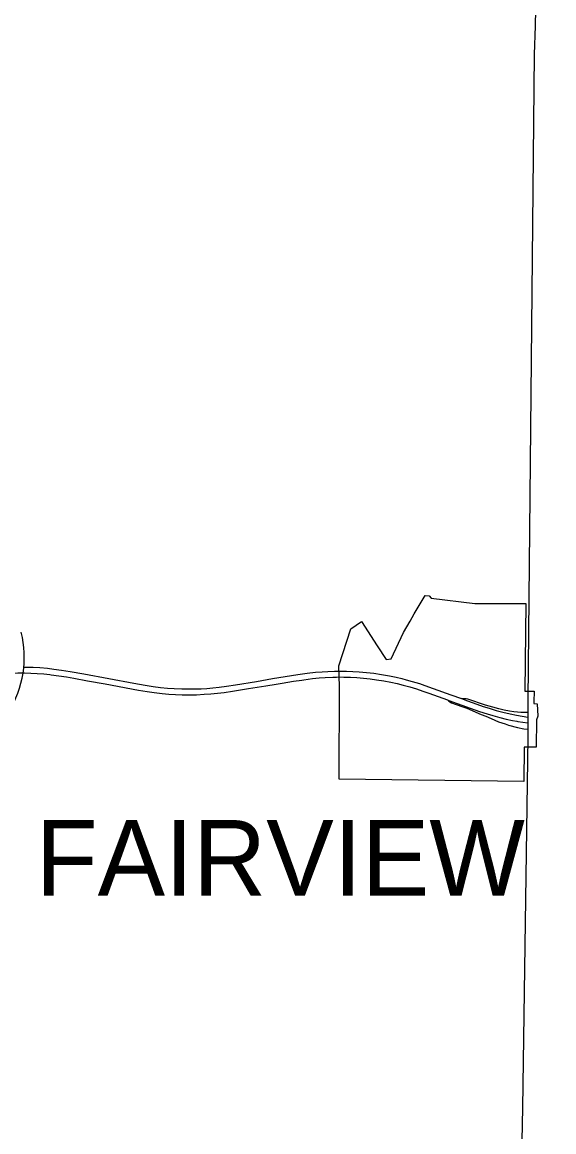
# Model space of a CAD drawing. Extents: x 1913970 to 2397567, y 78841 to 829347.
# Drawn here: x 2316499 to 2324369, y 745015 to 761443 of the extents above; entities that cross this region are included whole.
import ezdxf

# ---------------------------------------------------------------- set-up
doc = ezdxf.new("R2010")
doc.units = 0
for name, color, linetype in [('GM_X_Corporation', 7, 'Continuous'), ('GM_X_Corporation_Text', 7, 'Continuous'), ('GM_X_County', 7, 'Continuous'), ('GM_X_Interstate_Route', 7, 'Continuous'), ('GM_X_Interstate_Shield', 7, 'Continuous'), ('UT_P_Electric', 7, 'Continuous')]:
    doc.layers.add(name, color=color, linetype=linetype)

msp = doc.modelspace()

# ---------------------------------------------------------------- linework, layer by layer
at = {"layer": 'GM_X_Corporation'}
msp.add_lwpolyline([(2321188, 751913), (2321365, 752464), (2321521, 752570), (2321754, 752210), (2321887, 752009), (2321963, 752018), (2322144, 752405), (2322245, 752573), (2322303, 752684), (2322466, 752956), (2322522, 752949), (2322555, 752914), (2323198, 752837), (2323954, 752835), (2323938, 751538), (2324080, 751538), (2324073, 751383), (2324072, 751356), (2324123, 751353), (2324135, 751167), (2324115, 751113), (2324110, 750712), (2323930, 750710), (2323925, 750203), (2321191, 750235), (2321195, 751610)], close=True, dxfattribs=at)
at = {"layer": 'GM_X_County'}
msp.add_lwpolyline([(2324369, 779084), (2324336, 777711), (2324310, 776695), (2324256, 773858), (2324222, 769713), (2324164, 766356), (2324112, 762364), (2324091, 761387), (2324077, 760963), (2323984, 751408), (2323984, 751226), (2323984, 751159), (2323984, 751073), (2323984, 750978), (2323984, 750856), (2323908, 745369), (2323896, 744883)], dxfattribs=at)
at = {"layer": 'GM_X_Interstate_Route'}
for points in [[(2315028, 751513), (2315142, 751557), (2315263, 751601), (2315365, 751636), (2315459, 751665), (2315554, 751691), (2315656, 751715), (2315756, 751736), (2315853, 751754), (2315950, 751769), (2316045, 751782), (2316139, 751793), (2316231, 751800), (2316336, 751806), (2316434, 751809), (2316533, 751809), (2316628, 751806), (2316723, 751801), (2316821, 751793), (2316909, 751784)], [(2316909, 751784), (2316929, 751782), (2317040, 751767), (2317157, 751749), (2317263, 751731), (2317467, 751693), (2317728, 751645), (2318222, 751554), (2318348, 751533), (2318455, 751518), (2318572, 751505), (2318670, 751496), (2318768, 751489), (2318869, 751486), (2318971, 751485), (2319082, 751487), (2319194, 751492), (2319292, 751499), (2319390, 751507), (2319487, 751519), (2319611, 751537), (2319850, 751577), (2320106, 751619), (2320258, 751644), (2320349, 751658), (2320514, 751685), (2320638, 751704)], [(2320638, 751704), (2320669, 751709), (2320796, 751725), (2320894, 751735), (2320983, 751742), (2321098, 751747), (2321152, 751748), (2321183, 751749)], [(2321183, 751749), (2321188, 751749), (2321263, 751748), (2321360, 751745), (2321455, 751739), (2321554, 751731), (2321651, 751720), (2321746, 751707), (2321853, 751690), (2321959, 751671), (2322052, 751650), (2322141, 751628), (2322239, 751601), (2322337, 751572), (2322430, 751541), (2322520, 751509), (2322796, 751409)], [(2322796, 751409), (2322816, 751402), (2323130, 751289), (2323270, 751240), (2323385, 751203), (2323469, 751177), (2323570, 751150), (2323666, 751126), (2323759, 751106), (2323823, 751093), (2323839, 751090), (2323985, 751070)]]:
    msp.add_lwpolyline(points, dxfattribs=at)
at = {"layer": 'GM_X_Interstate_Shield'}
msp.add_arc((2315022, 752040), 1509, 281.537, 14.1934, dxfattribs=at)
at = {"layer": 'UT_P_Electric'}
for points in [[(2316514, 751809), (2316533, 751809), (2316628, 751806), (2316723, 751801), (2316821, 751793), (2316909, 751784)], [(2316524, 751896), (2316558, 751895), (2316663, 751892), (2316761, 751887), (2316872, 751878), (2316970, 751866), (2317080, 751850), (2317209, 751829), (2317410, 751793), (2318152, 751656), (2318320, 751626), (2318440, 751608), (2318547, 751595), (2318652, 751585), (2318750, 751578), (2318862, 751573), (2318974, 751571), (2319062, 751572), (2319148, 751575), (2319233, 751580), (2319321, 751587), (2319416, 751598), (2319523, 751612), (2319657, 751632), (2319967, 751684), (2320207, 751724), (2320582, 751784), (2320719, 751803), (2320842, 751818), (2320940, 751826), (2321025, 751831), (2321125, 751834), (2321186, 751834), (2321257, 751834), (2321299, 751834), (2321394, 751831), (2321489, 751825), (2321596, 751816), (2321707, 751803), (2321817, 751786), (2321939, 751765), (2322036, 751745), (2322119, 751726), (2322182, 751709), (2322270, 751684), (2322380, 751650), (2322460, 751623), (2322584, 751579), (2322847, 751486), (2323004, 751428)], [(2316909, 751784), (2316929, 751782), (2317040, 751767), (2317157, 751749), (2317263, 751731), (2317467, 751693), (2317728, 751645), (2318222, 751554), (2318348, 751533), (2318455, 751518), (2318572, 751505), (2318670, 751496), (2318768, 751489), (2318869, 751486), (2318971, 751485), (2319082, 751487), (2319194, 751492), (2319292, 751499), (2319390, 751507), (2319487, 751519), (2319611, 751537), (2319850, 751577), (2320106, 751619), (2320258, 751644), (2320349, 751658), (2320514, 751685), (2320638, 751704)], [(2320638, 751704), (2320669, 751709), (2320796, 751725), (2320894, 751735), (2320983, 751742), (2321098, 751747), (2321152, 751748), (2321183, 751749)], [(2321183, 751749), (2321188, 751749), (2321263, 751748), (2321360, 751745), (2321455, 751739), (2321554, 751731), (2321651, 751720), (2321746, 751707), (2321853, 751690), (2321959, 751671), (2322052, 751650), (2322141, 751628), (2322239, 751601), (2322337, 751572), (2322430, 751541), (2322520, 751509), (2322796, 751409)], [(2322796, 751409), (2322817, 751390), (2322831, 751381), (2322856, 751368), (2323009, 751312), (2323080, 751285), (2323295, 751195), (2323361, 751167), (2323440, 751134), (2323552, 751087), (2323648, 751053), (2323697, 751037), (2323830, 751003), (2323926, 750983), (2323985, 750976)], [(2322796, 751409), (2322816, 751402), (2323130, 751289), (2323270, 751240), (2323385, 751203), (2323469, 751177), (2323570, 751150), (2323666, 751126), (2323759, 751106), (2323823, 751093), (2323839, 751090), (2323985, 751070)], [(2323985, 751223), (2323881, 751223), (2323832, 751226), (2323776, 751232), (2323711, 751243), (2323634, 751258), (2323554, 751277), (2323469, 751300), (2323359, 751333), (2323095, 751419), (2323070, 751425), (2323039, 751427), (2323004, 751428)], [(2323004, 751428), (2323093, 751395), (2323229, 751346), (2323322, 751314), (2323413, 751286), (2323517, 751255), (2323615, 751229), (2323721, 751204), (2323817, 751184), (2323901, 751168), (2323985, 751156)]]:
    msp.add_lwpolyline(points, dxfattribs=at)

# ---------------------------------------------------------------- texts
at = {"layer": 'GM_X_Corporation_Text'}
msp.add_text('FAIRVIEW', height=1120, rotation=0, dxfattribs=at).set_placement((2316701, 748510))

doc.saveas('drawing.dxf')
